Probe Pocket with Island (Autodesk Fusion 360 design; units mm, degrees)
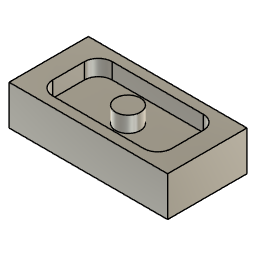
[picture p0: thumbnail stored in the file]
sketch "Sketch1" plane through (0, 0, 0) normal (0, 0, 1) x axis (1, 0, 0)
  line L1 (-50.8, -25.4) -> (50.8, -25.4)
  line L2 (-50.8, 25.4) -> (-50.8, -25.4)
  line L3 (50.8, 25.4) -> (-50.8, 25.4)
  line L4 (50.8, -25.4) -> (50.8, 25.4)
  line L5 (-50.8, 25.4) -> (50.8, -25.4)
  line L6 (50.8, 25.4) -> (-50.8, -25.4)
  point P6 (0, 0)
  point P1 (0, 0)
  point P4 (-50.8, 25.4)
  point P5 (50.8, 25.4)
  point P3 (-50.8, -25.4)
  horizontal L1
  perpendicular L1 L2
  parallel L1 L3
  parallel L2 L4
  coincident L5 P6
  coincident L6 P6
  coincident P1 P6
  dimension "d1" distance P4 P5 = 101.6
  dimension "d2" distance P3 P4 = 50.8
extrude "Extrude1" new body sketch "Sketch1" profile of L1 L2 L3 L4 along normal blind 25.4
sketch "Sketch2" plane through (0, 0, 25.4) normal (0, 0, 1) x axis (-1, 0, 0)
  line L1 (50.8, -25.4) -> (-50.8, -25.4)
  line L2 (50.8, 25.4) -> (50.8, -25.4)
  line L3 (-50.8, 25.4) -> (50.8, 25.4)
  line L4 (-50.8, -25.4) -> (-50.8, 25.4)
  line L5 (38.1, 19.05) -> (-38.1, 19.05)
  line L6 (38.1, -19.05) -> (38.1, 19.05)
  line L7 (-38.1, -19.05) -> (38.1, -19.05)
  line L8 (-38.1, 19.05) -> (-38.1, -19.05)
  line L9 (38.1, -19.05) -> (-38.1, 19.05)
  line L10 (-38.1, -19.05) -> (38.1, 19.05)
  circle C1 centre (0, 0) radius 7.9375
  point P10 (0, 0)
  point P1 (0, 0)
  point P11 (0, 0)
  point P8 (38.1, -19.05)
  point P9 (-38.1, -19.05)
  point P7 (38.1, 19.05)
  horizontal L5
  perpendicular L5 L6
  parallel L5 L7
  parallel L6 L8
  coincident L9 P10
  coincident L10 P10
  coincident P1 P10
  coincident P1 P11
  dimension "d5" distance P8 P9 = 76.2
  dimension "d6" distance P7 P8 = 38.1
  dimension "d7" diameter C1 = 15.875
extrude "Extrude2" cut sketch "Sketch2" profile of L5 L6 L7 L8 C1 against normal blind 10.16
fillet "Fillet1" radius 8.89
